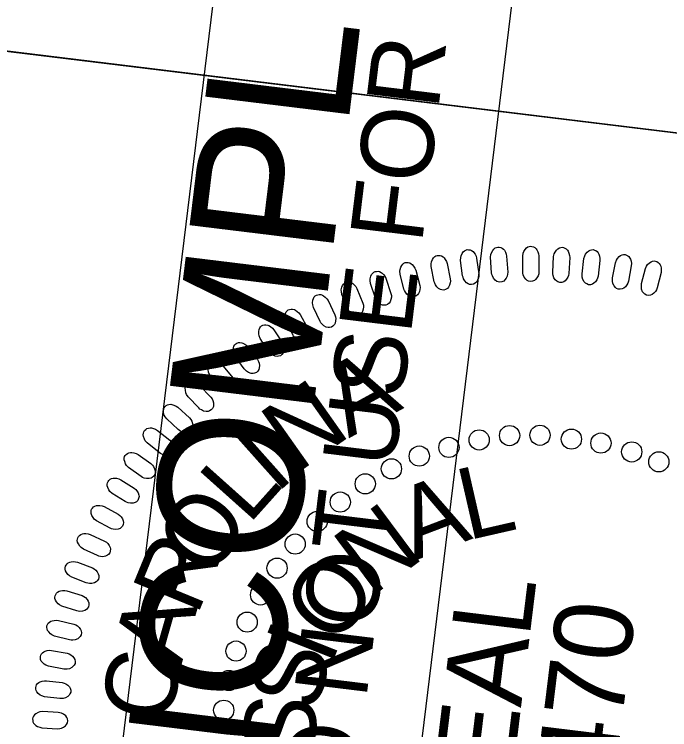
# Model space of a CAD drawing. Extents: x 480344 to 482186, y 488805 to 491553.
# Drawn here: x 480882.7 to 480934.7, y 490429.6 to 490486.4 of the extents above; entities that cross this region are included whole.
import ezdxf

# ---------------------------------------------------------------- set-up
doc = ezdxf.new("R2010")
doc.units = 0
for name, color, linetype in [('Sheet PE Seal Cell', 7, 'Continuous'), ('Sheet Plan CELL', 7, 'Continuous'), ('Sheet Sticker Incomplete CELL', 7, 'Continuous')]:
    doc.layers.add(name, color=color, linetype=linetype)

msp = doc.modelspace()

# ---------------------------------------------------------------- linework, layer by layer
at = {"layer": 'Sheet PE Seal Cell'}
for points in [[(480918.271, 490465.623), (480918.113, 490466.839), (480918.122, 490467.061), (480918.155, 490467.207), (480918.245, 490467.39), (480918.327, 490467.511), (480918.428, 490467.604), (480918.526, 490467.657), (480918.635, 490467.692), (480918.749, 490467.687), (480918.872, 490467.672), (480918.982, 490467.627), (480919.099, 490467.541), (480919.169, 490467.47), (480919.255, 490467.33), (480919.338, 490467.159), (480919.381, 490467.004), (480919.55, 490465.759), (480919.55, 490465.588), (480919.523, 490465.444), (480919.455, 490465.274), (480919.362, 490465.121), (480919.276, 490465.029), (480919.128, 490464.95), (480918.982, 490464.911), (480918.829, 490464.931), (480918.719, 490464.967), (480918.58, 490465.05), (480918.439, 490465.202), (480918.349, 490465.372), (480918.303, 490465.497)], [(480920.571, 490465.856), (480920.489, 490467.079), (480920.512, 490467.301), (480920.554, 490467.444), (480920.655, 490467.62), (480920.745, 490467.736), (480920.852, 490467.824), (480920.953, 490467.87), (480921.064, 490467.898), (480921.177, 490467.885), (480921.299, 490467.863), (480921.406, 490467.81), (480921.517, 490467.718), (480921.583, 490467.643), (480921.66, 490467.497), (480921.731, 490467.322), (480921.764, 490467.165), (480921.856, 490465.911), (480921.844, 490465.74), (480921.809, 490465.598), (480921.73, 490465.433), (480921.627, 490465.287), (480921.536, 490465.2), (480921.383, 490465.13), (480921.235, 490465.1), (480921.084, 490465.13), (480920.976, 490465.173), (480920.842, 490465.264), (480920.712, 490465.425), (480920.632, 490465.6), (480920.594, 490465.727)], [(480923.04, 490465.955), (480923.036, 490467.182), (480923.072, 490467.401), (480923.124, 490467.541), (480923.235, 490467.711), (480923.332, 490467.822), (480923.444, 490467.902), (480923.548, 490467.942), (480923.66, 490467.962), (480923.772, 490467.942), (480923.892, 490467.913), (480923.998, 490467.854), (480924.102, 490467.754), (480924.162, 490467.675), (480924.23, 490467.525), (480924.291, 490467.346), (480924.314, 490467.186), (480924.326, 490465.93), (480924.304, 490465.76), (480924.26, 490465.62), (480924.171, 490465.461), (480924.059, 490465.321), (480923.962, 490465.24), (480923.806, 490465.18), (480923.656, 490465.16), (480923.506, 490465.199), (480923.402, 490465.249), (480923.274, 490465.348), (480923.154, 490465.517), (480923.086, 490465.696), (480923.056, 490465.826)], [(480925.417, 490465.91), (480925.49, 490467.135), (480925.54, 490467.351), (480925.6, 490467.488), (480925.722, 490467.651), (480925.825, 490467.754), (480925.943, 490467.827), (480926.049, 490467.86), (480926.162, 490467.874), (480926.273, 490467.847), (480926.391, 490467.811), (480926.491, 490467.745), (480926.59, 490467.639), (480926.645, 490467.556), (480926.704, 490467.403), (480926.753, 490467.219), (480926.766, 490467.059), (480926.699, 490465.804), (480926.666, 490465.636), (480926.613, 490465.499), (480926.514, 490465.345), (480926.394, 490465.213), (480926.293, 490465.139), (480926.132, 490465.088), (480925.982, 490465.077), (480925.835, 490465.126), (480925.733, 490465.182), (480925.612, 490465.289), (480925.503, 490465.465), (480925.446, 490465.649), (480925.424, 490465.78)], [(480927.748, 490465.775), (480927.898, 490466.994), (480927.961, 490467.206), (480928.03, 490467.339), (480928.162, 490467.494), (480928.272, 490467.591), (480928.393, 490467.656), (480928.501, 490467.683), (480928.615, 490467.689), (480928.724, 490467.655), (480928.839, 490467.611), (480928.936, 490467.539), (480929.027, 490467.427), (480929.077, 490467.341), (480929.126, 490467.184), (480929.163, 490466.999), (480929.166, 490466.838), (480929.021, 490465.589), (480928.978, 490465.424), (480928.916, 490465.291), (480928.808, 490465.143), (480928.68, 490465.019), (480928.574, 490464.951), (480928.41, 490464.91), (480928.26, 490464.909), (480928.116, 490464.967), (480928.019, 490465.029), (480927.904, 490465.143), (480927.807, 490465.327), (480927.761, 490465.513), (480927.747, 490465.645)], [(480916.024, 490465.147), (480915.789, 490466.351), (480915.784, 490466.574), (480915.809, 490466.721), (480915.887, 490466.909), (480915.961, 490467.035), (480916.056, 490467.135), (480916.15, 490467.194), (480916.257, 490467.235), (480916.371, 490467.237), (480916.494, 490467.23), (480916.608, 490467.191), (480916.73, 490467.113), (480916.804, 490467.047), (480916.899, 490466.912), (480916.992, 490466.748), (480917.045, 490466.595), (480917.292, 490465.363), (480917.302, 490465.193), (480917.284, 490465.047), (480917.227, 490464.874), (480917.144, 490464.715), (480917.063, 490464.618), (480916.921, 490464.529), (480916.778, 490464.481), (480916.623, 490464.492), (480916.512, 490464.521), (480916.367, 490464.594), (480916.218, 490464.737), (480916.117, 490464.901), (480916.063, 490465.023)], [(480930.167, 490465.447), (480930.392, 490466.653), (480930.469, 490466.861), (480930.546, 490466.989), (480930.688, 490467.136), (480930.803, 490467.226), (480930.928, 490467.283), (480931.038, 490467.303), (480931.153, 490467.302), (480931.258, 490467.262), (480931.371, 490467.21), (480931.463, 490467.133), (480931.547, 490467.015), (480931.591, 490466.926), (480931.63, 490466.766), (480931.656, 490466.579), (480931.649, 490466.417), (480931.425, 490465.181), (480931.372, 490465.019), (480931.302, 490464.89), (480931.185, 490464.749), (480931.049, 490464.633), (480930.939, 490464.572), (480930.773, 490464.542), (480930.622, 490464.55), (480930.483, 490464.617), (480930.389, 490464.685), (480930.283, 490464.806), (480930.196, 490464.995), (480930.163, 490465.184), (480930.158, 490465.316)], [(480913.621, 490464.56), (480913.311, 490465.747), (480913.292, 490465.969), (480913.307, 490466.117), (480913.373, 490466.309), (480913.44, 490466.44), (480913.528, 490466.545), (480913.619, 490466.611), (480913.723, 490466.658), (480913.836, 490466.667), (480913.959, 490466.668), (480914.075, 490466.637), (480914.202, 490466.566), (480914.28, 490466.505), (480914.383, 490466.377), (480914.486, 490466.218), (480914.548, 490466.07), (480914.872, 490464.855), (480914.894, 490464.686), (480914.885, 490464.539), (480914.839, 490464.362), (480914.766, 490464.199), (480914.692, 490464.097), (480914.555, 490463.999), (480914.415, 490463.943), (480914.261, 490463.943), (480914.147, 490463.965), (480913.998, 490464.029), (480913.84, 490464.164), (480913.729, 490464.32), (480913.668, 490464.439)], [(480932.469, 490464.998), (480932.77, 490466.187), (480932.86, 490466.391), (480932.944, 490466.513), (480933.095, 490466.651), (480933.216, 490466.733), (480933.344, 490466.783), (480933.455, 490466.796), (480933.569, 490466.787), (480933.673, 490466.741), (480933.782, 490466.682), (480933.868, 490466.599), (480933.945, 490466.477), (480933.984, 490466.385), (480934.012, 490466.223), (480934.026, 490466.035), (480934.009, 490465.874), (480933.708, 490464.654), (480933.645, 490464.495), (480933.567, 490464.371), (480933.441, 490464.238), (480933.298, 490464.13), (480933.185, 490464.077), (480933.018, 490464.057), (480932.868, 490464.074), (480932.733, 490464.15), (480932.643, 490464.224), (480932.544, 490464.351), (480932.471, 490464.545), (480932.449, 490464.736), (480932.452, 490464.869)], [(480911.357, 490463.85), (480910.973, 490465.015), (480910.94, 490465.235), (480910.946, 490465.384), (480911, 490465.58), (480911.058, 490465.715), (480911.139, 490465.826), (480911.226, 490465.896), (480911.327, 490465.95), (480911.439, 490465.966), (480911.562, 490465.975), (480911.68, 490465.951), (480911.811, 490465.889), (480911.893, 490465.832), (480912.004, 490465.711), (480912.116, 490465.559), (480912.187, 490465.414), (480912.587, 490464.223), (480912.619, 490464.055), (480912.62, 490463.908), (480912.585, 490463.729), (480912.522, 490463.561), (480912.455, 490463.455), (480912.324, 490463.349), (480912.188, 490463.283), (480912.034, 490463.274), (480911.919, 490463.289), (480911.767, 490463.344), (480911.6, 490463.468), (480911.48, 490463.617), (480911.412, 490463.732)], [(480909.155, 490463.003), (480908.699, 490464.142), (480908.653, 490464.36), (480908.648, 490464.508), (480908.689, 490464.708), (480908.739, 490464.845), (480908.814, 490464.961), (480908.897, 490465.037), (480908.993, 490465.097), (480909.104, 490465.12), (480909.226, 490465.137), (480909.346, 490465.121), (480909.48, 490465.067), (480909.565, 490465.015), (480909.683, 490464.901), (480909.805, 490464.757), (480909.886, 490464.617), (480910.36, 490463.453), (480910.402, 490463.287), (480910.412, 490463.141), (480910.388, 490462.96), (480910.336, 490462.789), (480910.275, 490462.678), (480910.152, 490462.564), (480910.02, 490462.49), (480909.867, 490462.472), (480909.751, 490462.479), (480909.596, 490462.524), (480909.422, 490462.637), (480909.293, 490462.779), (480909.217, 490462.889)], [(480906.968, 490462), (480906.441, 490463.108), (480906.38, 490463.322), (480906.367, 490463.471), (480906.396, 490463.672), (480906.437, 490463.813), (480906.503, 490463.933), (480906.581, 490464.014), (480906.674, 490464.08), (480906.783, 490464.11), (480906.905, 490464.134), (480907.024, 490464.125), (480907.162, 490464.08), (480907.25, 490464.034), (480907.376, 490463.927), (480907.506, 490463.791), (480907.595, 490463.657), (480908.141, 490462.525), (480908.194, 490462.362), (480908.213, 490462.217), (480908.2, 490462.034), (480908.159, 490461.86), (480908.106, 490461.746), (480907.99, 490461.624), (480907.863, 490461.543), (480907.711, 490461.514), (480907.595, 490461.514), (480907.437, 490461.55), (480907.257, 490461.651), (480907.119, 490461.785), (480907.036, 490461.889)], [(480904.866, 490460.845), (480904.271, 490461.918), (480904.197, 490462.128), (480904.175, 490462.276), (480904.191, 490462.479), (480904.223, 490462.621), (480904.282, 490462.745), (480904.354, 490462.831), (480904.443, 490462.904), (480904.551, 490462.94), (480904.669, 490462.972), (480904.79, 490462.971), (480904.93, 490462.934), (480905.021, 490462.893), (480905.152, 490462.795), (480905.292, 490462.667), (480905.389, 490462.539), (480906.005, 490461.443), (480906.067, 490461.284), (480906.096, 490461.14), (480906.095, 490460.957), (480906.064, 490460.78), (480906.018, 490460.664), (480905.91, 490460.535), (480905.789, 490460.445), (480905.639, 490460.408), (480905.523, 490460.401), (480905.363, 490460.426), (480905.177, 490460.516), (480905.031, 490460.64), (480904.942, 490460.74)], [(480902.88, 490459.617), (480902.218, 490460.65), (480902.132, 490460.856), (480902.1, 490461.001), (480902.104, 490461.204), (480902.126, 490461.349), (480902.178, 490461.477), (480902.244, 490461.567), (480902.328, 490461.644), (480902.433, 490461.688), (480902.55, 490461.727), (480902.671, 490461.733), (480902.813, 490461.705), (480902.906, 490461.67), (480903.043, 490461.58), (480903.19, 490461.462), (480903.295, 490461.34), (480903.979, 490460.285), (480904.051, 490460.13), (480904.089, 490459.988), (480904.099, 490459.806), (480904.08, 490459.627), (480904.041, 490459.508), (480903.942, 490459.372), (480903.826, 490459.275), (480903.679, 490459.229), (480903.564, 490459.214), (480903.403, 490459.229), (480903.211, 490459.308), (480903.057, 490459.423), (480902.962, 490459.516)], [(480900.951, 490458.229), (480900.226, 490459.218), (480900.127, 490459.417), (480900.086, 490459.561), (480900.076, 490459.764), (480900.09, 490459.91), (480900.133, 490460.04), (480900.194, 490460.135), (480900.273, 490460.217), (480900.375, 490460.267), (480900.49, 490460.314), (480900.609, 490460.327), (480900.753, 490460.309), (480900.848, 490460.279), (480900.991, 490460.198), (480901.145, 490460.089), (480901.258, 490459.974), (480902.006, 490458.964), (480902.088, 490458.814), (480902.134, 490458.675), (480902.156, 490458.494), (480902.148, 490458.314), (480902.117, 490458.192), (480902.026, 490458.051), (480901.917, 490457.947), (480901.773, 490457.891), (480901.659, 490457.869), (480901.497, 490457.874), (480901.301, 490457.941), (480901.14, 490458.046), (480901.04, 490458.133)], [(480899.059, 490456.702), (480898.273, 490457.645), (480898.161, 490457.837), (480898.112, 490457.978), (480898.089, 490458.18), (480898.094, 490458.327), (480898.129, 490458.459), (480898.183, 490458.557), (480898.257, 490458.645), (480898.356, 490458.701), (480898.467, 490458.754), (480898.585, 490458.776), (480898.73, 490458.766), (480898.827, 490458.743), (480898.974, 490458.671), (480899.135, 490458.571), (480899.255, 490458.464), (480900.065, 490457.503), (480900.156, 490457.358), (480900.211, 490457.222), (480900.244, 490457.042), (480900.248, 490456.864), (480900.224, 490456.74), (480900.142, 490456.593), (480900.04, 490456.482), (480899.9, 490456.418), (480899.787, 490456.389), (480899.626, 490456.384), (480899.425, 490456.437), (480899.259, 490456.532), (480899.153, 490456.613)], [(480897.341, 490455.127), (480896.498, 490456.018), (480896.374, 490456.203), (480896.316, 490456.341), (480896.281, 490456.541), (480896.276, 490456.687), (480896.303, 490456.823), (480896.351, 490456.923), (480896.42, 490457.015), (480896.514, 490457.078), (480896.622, 490457.138), (480896.739, 490457.167), (480896.883, 490457.166), (480896.982, 490457.149), (480897.133, 490457.086), (480897.3, 490456.997), (480897.426, 490456.897), (480898.295, 490455.99), (480898.396, 490455.851), (480898.459, 490455.718), (480898.503, 490455.541), (480898.518, 490455.362), (480898.503, 490455.237), (480898.43, 490455.086), (480898.334, 490454.969), (480898.198, 490454.895), (480898.088, 490454.86), (480897.927, 490454.845), (480897.724, 490454.886), (480897.551, 490454.97), (480897.441, 490455.044)], [(480895.705, 490453.419), (480894.808, 490454.255), (480894.673, 490454.432), (480894.606, 490454.565), (480894.559, 490454.763), (480894.545, 490454.909), (480894.562, 490455.045), (480894.605, 490455.149), (480894.667, 490455.245), (480894.758, 490455.313), (480894.861, 490455.38), (480894.976, 490455.416), (480895.121, 490455.425), (480895.22, 490455.414), (480895.375, 490455.361), (480895.547, 490455.283), (480895.679, 490455.19), (480896.604, 490454.339), (480896.712, 490454.207), (480896.784, 490454.079), (480896.84, 490453.905), (480896.866, 490453.727), (480896.857, 490453.601), (480896.794, 490453.446), (480896.706, 490453.323), (480896.576, 490453.241), (480896.468, 490453.198), (480896.308, 490453.173), (480896.103, 490453.202), (480895.925, 490453.275), (480895.81, 490453.341)], [(480894.199, 490451.588), (480893.251, 490452.366), (480893.105, 490452.534), (480893.031, 490452.663), (480892.97, 490452.857), (480892.947, 490453.002), (480892.957, 490453.14), (480892.992, 490453.245), (480893.048, 490453.345), (480893.135, 490453.419), (480893.234, 490453.492), (480893.346, 490453.536), (480893.49, 490453.553), (480893.589, 490453.548), (480893.748, 490453.506), (480893.925, 490453.438), (480894.062, 490453.354), (480895.038, 490452.563), (480895.155, 490452.437), (480895.234, 490452.314), (480895.301, 490452.144), (480895.338, 490451.969), (480895.338, 490451.843), (480895.284, 490451.683), (480895.205, 490451.555), (480895.079, 490451.465), (480894.974, 490451.416), (480894.816, 490451.38), (480894.61, 490451.396), (480894.428, 490451.458), (480894.309, 490451.517)], [(480892.773, 490449.689), (480891.778, 490450.406), (480891.622, 490450.564), (480891.539, 490450.688), (480891.468, 490450.879), (480891.435, 490451.021), (480891.436, 490451.159), (480891.465, 490451.267), (480891.514, 490451.37), (480891.596, 490451.449), (480891.69, 490451.529), (480891.8, 490451.579), (480891.942, 490451.605), (480892.042, 490451.607), (480892.202, 490451.575), (480892.383, 490451.518), (480892.526, 490451.443), (480893.549, 490450.714), (480893.674, 490450.597), (480893.761, 490450.479), (480893.838, 490450.313), (480893.886, 490450.14), (480893.894, 490450.015), (480893.85, 490449.852), (480893.779, 490449.719), (480893.66, 490449.621), (480893.557, 490449.565), (480893.402, 490449.521), (480893.195, 490449.523), (480893.01, 490449.573), (480892.887, 490449.625)], [(480891.508, 490447.703), (480890.47, 490448.357), (480890.304, 490448.505), (480890.214, 490448.624), (480890.13, 490448.809), (480890.089, 490448.95), (480890.081, 490449.087), (480890.103, 490449.197), (480890.146, 490449.303), (480890.223, 490449.386), (480890.311, 490449.472), (480890.418, 490449.529), (480890.558, 490449.564), (480890.657, 490449.572), (480890.82, 490449.549), (480891.004, 490449.505), (480891.151, 490449.439), (480892.218, 490448.776), (480892.35, 490448.667), (480892.444, 490448.554), (480892.532, 490448.393), (480892.59, 490448.224), (480892.606, 490448.099), (480892.573, 490447.934), (480892.51, 490447.797), (480892.397, 490447.692), (480892.299, 490447.63), (480892.146, 490447.575), (480891.94, 490447.565), (480891.751, 490447.603), (480891.626, 490447.647)], [(480890.309, 490445.592), (480889.232, 490446.179), (480889.057, 490446.317), (480888.959, 490446.429), (480888.864, 490446.609), (480888.814, 490446.747), (480888.798, 490446.883), (480888.813, 490446.994), (480888.849, 490447.103), (480888.92, 490447.191), (480889.004, 490447.282), (480889.107, 490447.345), (480889.244, 490447.39), (480889.343, 490447.404), (480889.506, 490447.391), (480889.693, 490447.358), (480889.843, 490447.302), (480890.951, 490446.707), (480891.089, 490446.605), (480891.19, 490446.5), (480891.287, 490446.345), (480891.356, 490446.179), (480891.38, 490446.056), (480891.357, 490445.889), (480891.303, 490445.748), (480891.196, 490445.636), (480891.103, 490445.568), (480890.954, 490445.504), (480890.748, 490445.481), (480890.558, 490445.507), (480890.43, 490445.543)], [(480889.303, 490443.414), (480888.191, 490443.933), (480888.007, 490444.059), (480887.904, 490444.166), (480887.797, 490444.339), (480887.739, 490444.473), (480887.713, 490444.608), (480887.722, 490444.72), (480887.751, 490444.83), (480887.816, 490444.923), (480887.894, 490445.019), (480887.993, 490445.089), (480888.127, 490445.141), (480888.225, 490445.162), (480888.389, 490445.16), (480888.577, 490445.138), (480888.731, 490445.091), (480889.873, 490444.567), (480890.018, 490444.476), (480890.125, 490444.376), (480890.232, 490444.227), (480890.311, 490444.066), (480890.342, 490443.945), (480890.33, 490443.777), (480890.284, 490443.633), (480890.186, 490443.514), (480890.096, 490443.441), (480889.952, 490443.368), (480889.748, 490443.331), (480889.557, 490443.345), (480889.427, 490443.374)], [(480888.413, 490441.257), (480887.27, 490441.703), (480887.08, 490441.818), (480886.969, 490441.918), (480886.851, 490442.084), (480886.785, 490442.215), (480886.752, 490442.348), (480886.753, 490442.46), (480886.775, 490442.572), (480886.834, 490442.669), (480886.906, 490442.77), (480886.999, 490442.845), (480887.13, 490442.906), (480887.226, 490442.933), (480887.391, 490442.941), (480887.58, 490442.931), (480887.737, 490442.895), (480888.909, 490442.443), (480889.059, 490442.36), (480889.172, 490442.267), (480889.288, 490442.126), (480889.378, 490441.97), (480889.417, 490441.851), (480889.415, 490441.683), (480889.379, 490441.537), (480889.287, 490441.412), (480889.203, 490441.333), (480889.064, 490441.251), (480888.862, 490441.201), (480888.67, 490441.204), (480888.539, 490441.223)], [(480887.663, 490439.026), (480886.495, 490439.4), (480886.297, 490439.503), (480886.181, 490439.595), (480886.053, 490439.754), (480885.979, 490439.88), (480885.937, 490440.011), (480885.931, 490440.123), (480885.946, 490440.236), (480885.999, 490440.336), (480886.064, 490440.441), (480886.153, 490440.523), (480886.28, 490440.592), (480886.374, 490440.624), (480886.537, 490440.643), (480886.727, 490440.645), (480886.886, 490440.618), (480888.084, 490440.241), (480888.238, 490440.167), (480888.358, 490440.082), (480888.482, 490439.948), (480888.581, 490439.799), (480888.628, 490439.682), (480888.636, 490439.514), (480888.61, 490439.366), (480888.526, 490439.236), (480888.447, 490439.151), (480888.313, 490439.061), (480888.115, 490438.999), (480887.924, 490438.989), (480887.791, 490439.001)], [(480887.095, 490436.738), (480885.906, 490437.039), (480885.702, 490437.129), (480885.58, 490437.214), (480885.443, 490437.364), (480885.36, 490437.485), (480885.31, 490437.614), (480885.297, 490437.724), (480885.305, 490437.838), (480885.352, 490437.942), (480885.41, 490438.05), (480885.494, 490438.137), (480885.617, 490438.214), (480885.708, 490438.253), (480885.87, 490438.282), (480886.059, 490438.295), (480886.219, 490438.278), (480887.439, 490437.977), (480887.598, 490437.914), (480887.722, 490437.837), (480887.855, 490437.711), (480887.963, 490437.568), (480888.016, 490437.454), (480888.036, 490437.287), (480888.019, 490437.137), (480887.943, 490437.002), (480887.87, 490436.913), (480887.742, 490436.813), (480887.548, 490436.739), (480887.357, 490436.718), (480887.224, 490436.721)], [(480886.635, 490434.415), (480885.429, 490434.64), (480885.22, 490434.716), (480885.092, 490434.794), (480884.946, 490434.935), (480884.856, 490435.051), (480884.798, 490435.176), (480884.779, 490435.286), (480884.78, 490435.4), (480884.82, 490435.506), (480884.871, 490435.618), (480884.949, 490435.71), (480885.066, 490435.795), (480885.156, 490435.839), (480885.315, 490435.878), (480885.502, 490435.904), (480885.663, 490435.897), (480886.9, 490435.673), (480887.063, 490435.62), (480887.192, 490435.55), (480887.332, 490435.432), (480887.448, 490435.297), (480887.51, 490435.187), (480887.539, 490435.021), (480887.532, 490434.87), (480887.465, 490434.731), (480887.396, 490434.637), (480887.275, 490434.531), (480887.087, 490434.444), (480886.898, 490434.411), (480886.764, 490434.406)], [(480886.322, 490432.076), (480885.105, 490432.225), (480884.892, 490432.289), (480884.759, 490432.358), (480884.605, 490432.49), (480884.507, 490432.6), (480884.442, 490432.721), (480884.415, 490432.829), (480884.409, 490432.943), (480884.442, 490433.052), (480884.486, 490433.167), (480884.558, 490433.263), (480884.67, 490433.355), (480884.757, 490433.405), (480884.914, 490433.453), (480885.099, 490433.491), (480885.26, 490433.494), (480886.508, 490433.349), (480886.674, 490433.306), (480886.807, 490433.244), (480886.954, 490433.136), (480887.08, 490433.007), (480887.147, 490432.901), (480887.187, 490432.738), (480887.188, 490432.588), (480887.131, 490432.444), (480887.069, 490432.347), (480886.955, 490432.232), (480886.771, 490432.134), (480886.585, 490432.089), (480886.453, 490432.075)], [(480886.196, 490430.968), (480884.971, 490431.04), (480884.75, 490431.016), (480884.608, 490430.972), (480884.432, 490430.87), (480884.317, 490430.78), (480884.23, 490430.672), (480884.184, 490430.57), (480884.158, 490430.459), (480884.171, 490430.346), (480884.194, 490430.225), (480884.247, 490430.117), (480884.341, 490430.007), (480884.417, 490429.943), (480884.562, 490429.866), (480884.738, 490429.796), (480884.896, 490429.764), (480886.15, 490429.683), (480886.32, 490429.695), (480886.462, 490429.732), (480886.627, 490429.811), (480886.773, 490429.916), (480886.859, 490430.007), (480886.928, 490430.161), (480886.957, 490430.309), (480886.925, 490430.461), (480886.881, 490430.568), (480886.789, 490430.701), (480886.627, 490430.83), (480886.452, 490430.908), (480886.324, 490430.946)]]:
    msp.add_lwpolyline(points, close=True, dxfattribs=at)
for centre in [(480919.586, 490452.592), (480921.996, 490452.939), (480924.408, 490452.964), (480926.899, 490452.659), (480917.186, 490452.003), (480929.242, 490452.343), (480914.836, 490451.311), (480931.684, 490451.642), (480933.836, 490450.858), (480912.625, 490450.298), (480910.552, 490449.108), (480908.57, 490447.666), (480906.736, 490446.126), (480904.991, 490444.334), (480903.553, 490442.424), (480902.249, 490440.298), (480901.182, 490438.142), (480900.299, 490435.844), (480899.732, 490433.507), (480899.323, 490431.15)]:
    msp.add_circle(centre, 0.801, dxfattribs=at)
at = {"layer": 'Sheet Plan CELL'}
msp.add_line((480865.278, 490485.486), (480976.913, 490471.864), dxfattribs=at)
for points in [[(480865.278, 490485.486), (480877.388, 490584.738), (480989.072, 490571.11), (480976.961, 490471.846)], [(480853.149, 490386.174), (480865.278, 490485.486), (480976.961, 490471.846), (480964.808, 490372.549)]]:
    msp.add_lwpolyline(points, close=True, dxfattribs=at)
at = {"layer": 'Sheet Sticker Incomplete CELL'}
msp.add_lwpolyline([(480912.202, 490405.709), (480888.876, 490408.558), (480906.698, 490554.474), (480930.024, 490551.625)], close=True, dxfattribs=at)

# ---------------------------------------------------------------- texts
at = {"layer": 'Sheet PE Seal Cell'}
for s, height, rotation, p in [('A', 5.669, 28.7093, (480909.24, 490452.712)), ('N', 5.669, 35.1987, (480905.085, 490449.875)), ('I', 5.669, 41.688, (480903.457, 490448.256)), ('L', 5.669, 48.1774, (480901.291, 490445.807)), ('L', 5.669, 12.8674, (480918.662, 490444.618)), ('A', 5.669, 20.8072, (480914.439, 490442.995)), ('O', 5.669, 54.6668, (480898.204, 490441.416)), ('N', 5.669, 36.6868, (480910.976, 490440.056)), ('R', 5.669, 67.6455, (480897.197, 490438.562)), ('O', 5.669, 52.5664, (480908.166, 490436.055)), ('SEAL', 6.2363, 83.0179, (480921.543, 490420.268)), ('29470', 6.2363, 83.0179, (480929.202, 490416.34)), ('A', 5.669, 74.1348, (480895.899, 490434.483)), ('I', 5.669, 68.4459, (480907.814, 490434.584)), ('S', 5.669, 76.3857, (480906.726, 490430.888)), ('C', 5.669, 80.6242, (480895.137, 490429.967)), ('S', 5.669, 84.3255, (480906.358, 490427.043))]:
    msp.add_text(s, height=height, rotation=rotation, dxfattribs=at).set_placement(p)
at = {"layer": 'Sheet Sticker Incomplete CELL'}
for s, height, p in [('INCOMPLETE PLANS', 11.52, (480901.674, 490416.012)), ('DO NOT USE FOR R/W ACQUISITION', 5.76, (480908.967, 490418.395))]:
    msp.add_text(s, height=height, rotation=83.0365, dxfattribs=at).set_placement(p)

doc.saveas('drawing.dxf')
